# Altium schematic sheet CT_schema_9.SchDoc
size 308 x 210 mm
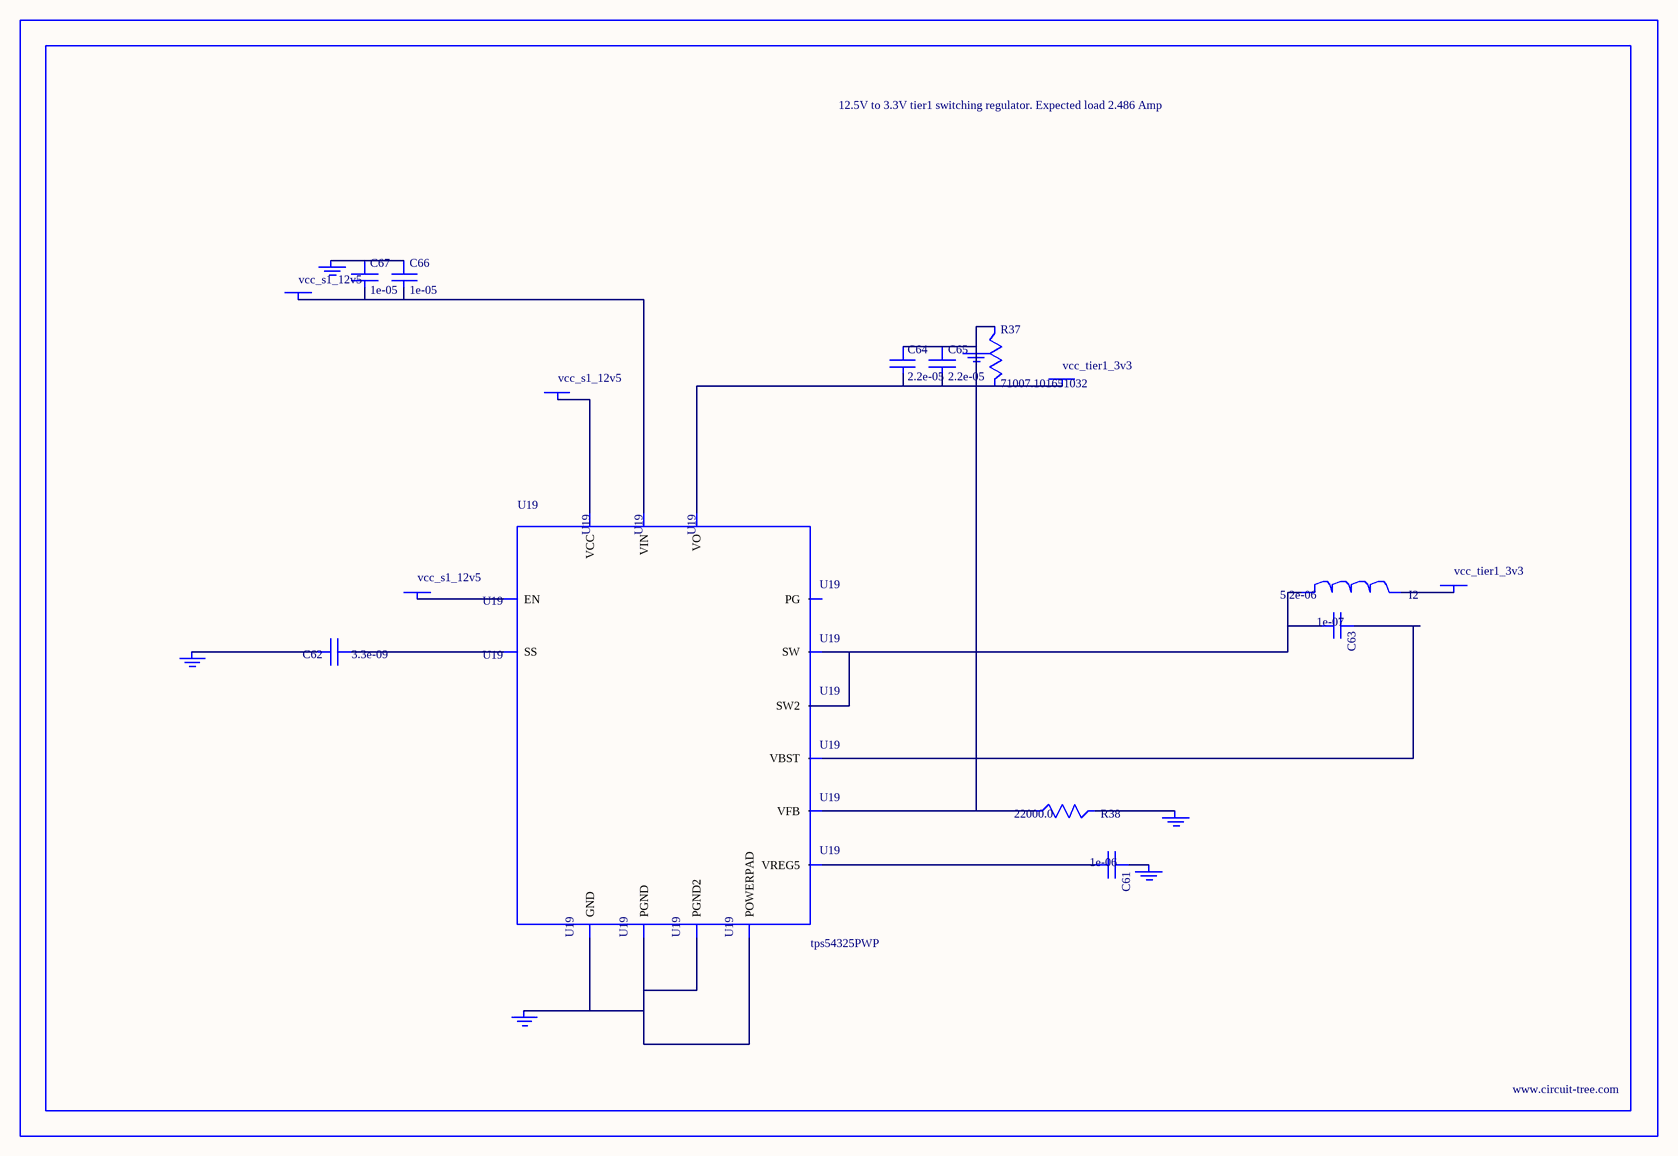
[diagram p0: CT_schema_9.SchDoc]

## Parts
BORDER8  (no value)
C61  1e-06  [C0603]
C62  3.3e-09  [C0402]
C63  1e-07  [C0402]
C64  2.2e-05  [C1210]
C65  2.2e-05  [C1210]
C66  1e-05  [C1206]
C67  1e-05  [C1206]
GND_INSTANCE_8_0  (no value)
GND_INSTANCE_8_1  (no value)
GND_INSTANCE_8_2  (no value)
GND_INSTANCE_8_3  (no value)
GND_INSTANCE_8_4  (no value)
GND_INSTANCE_8_5  (no value)
I2  5.2e-06  [DR1040]
POWER_INSTANCE_8_0  vcc_tier1_3v3
POWER_INSTANCE_8_1  vcc_s1_12v5
POWER_INSTANCE_8_2  vcc_tier1_3v3
POWER_INSTANCE_8_3  vcc_s1_12v5
POWER_INSTANCE_8_4  vcc_s1_12v5
R37  71007.101651032  [R0603]
R38  22000.0  [R0603]
U19  tps54325PWP  [HTSSOP14]

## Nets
NetC61_1: C61.1 GND_INSTANCE_8_2.0(GND)
NetC61_2: C61.2 U19.3(VREG5)
NetC62_1: C62.1 U19.4(SS)
NetC62_2: C62.2 GND_INSTANCE_8_3.0(GND)
NetC63_1: C63.1 U19.12(VBST)
NetC63_2: C63.2 I2.1 U19.10(SW) U19.11(SW2)
NetC64_1: C64.1 C65.1 GND_INSTANCE_8_0.0(GND) R37.1 R38.1 U19.2(VFB)
NetC64_2: C64.2 C65.2 POWER_INSTANCE_8_0.0(PWR) R37.2 U19.1(VO)
NetC66_1: C66.1 C67.1 GND_INSTANCE_8_5.0(GND)
NetC66_2: C66.2 C67.2 POWER_INSTANCE_8_3.0(PWR) U19.13(VIN)
NetGND_INSTANCE_8_1_0: GND_INSTANCE_8_1.0(GND) R38.2
NetGND_INSTANCE_8_4_0: GND_INSTANCE_8_4.0(GND) U19.5(GND) U19.8(PGND) U19.9(PGND2) U19.15(POWERPAD)
NetI2_2: I2.2 POWER_INSTANCE_8_2.0(PWR)
NetPOWER_INSTANCE_8_1_0: POWER_INSTANCE_8_1.0(PWR) U19.7(EN)
NetPOWER_INSTANCE_8_4_0: POWER_INSTANCE_8_4.0(PWR) U19.14(VCC)

Not connected (* = marked no-connect by the designer): U19 6(PG)

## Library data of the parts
BORDER8 = BORDER_PAGE8
C61 = C0603C105K3RACTU
C62 = C0402C332K3RAC
C63 = C0402C104K3RACTU
C64 C65 = GRM32ER61E226ME15L
C66 C67 = C1206C106K3RACTU
GND_INSTANCE_8_0-GND_INSTANCE_8_5 = GND
I2 = DR1040-5R2-R
POWER_INSTANCE_8_0-POWER_INSTANCE_8_4 = PWR
R37 = R37
R38 = RC0603JR-0722KL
